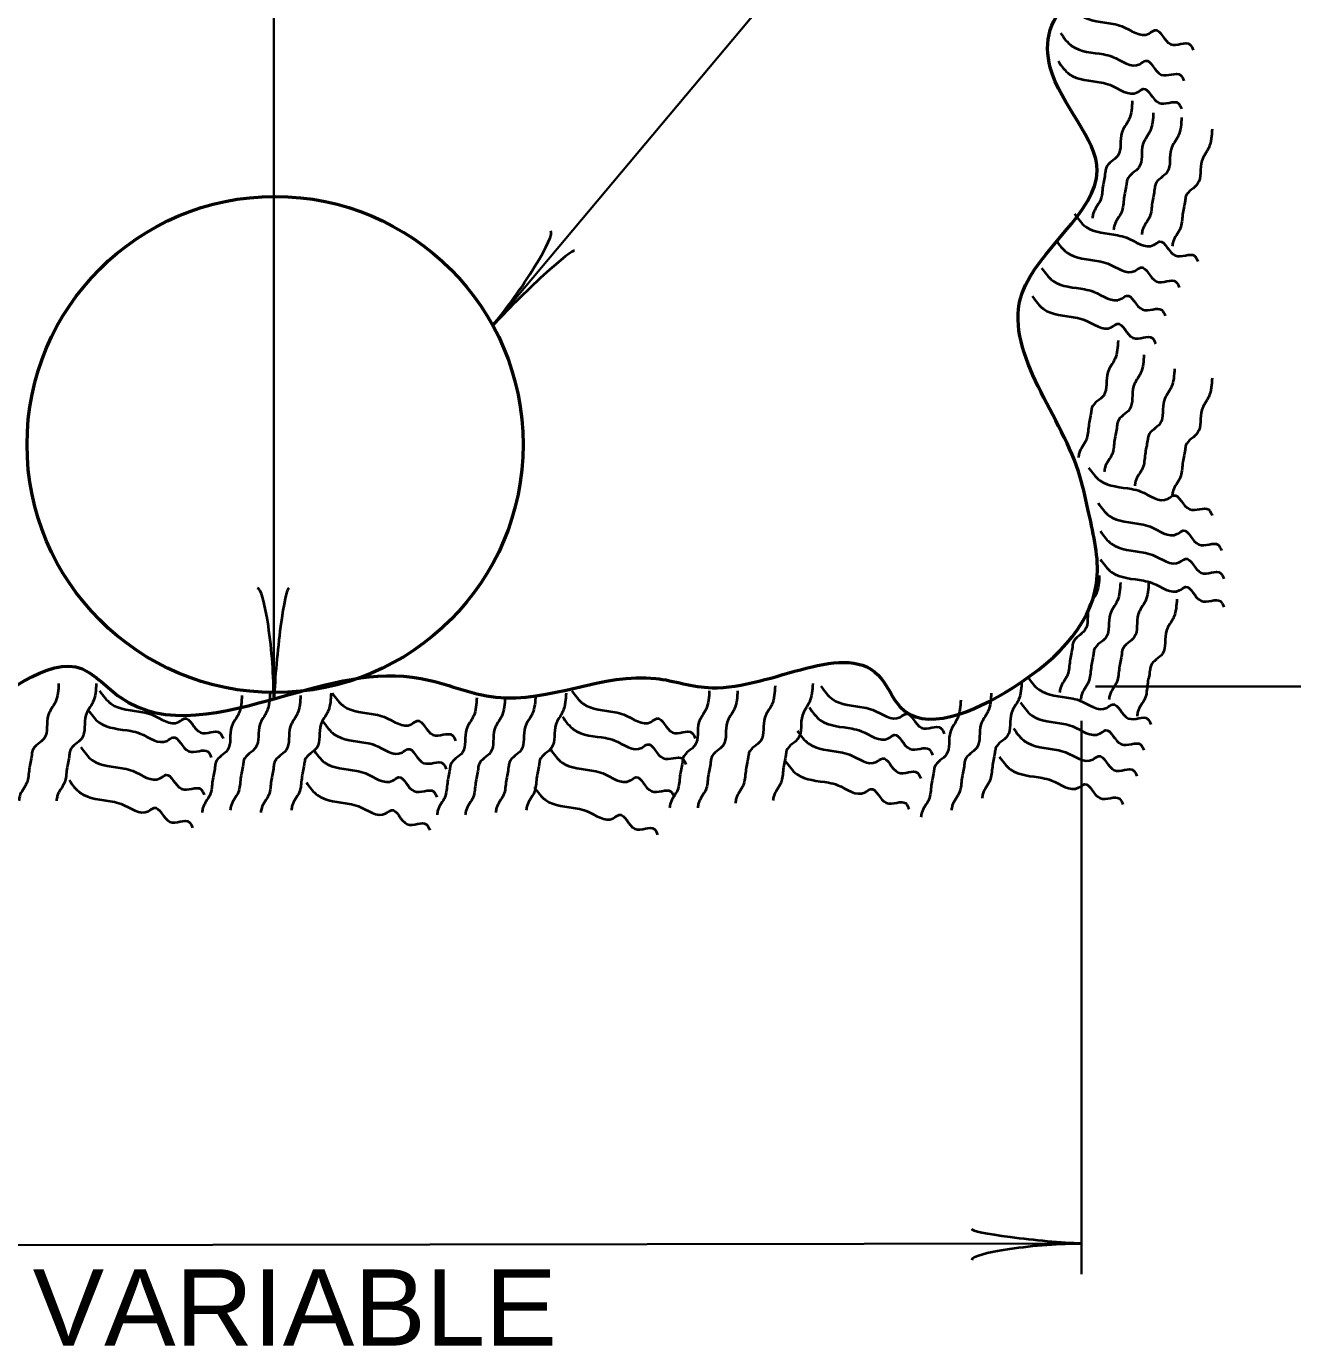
# Model space of a CAD drawing. Extents: x -488 to 193, y 19 to 459.
# Drawn here: x -199.23 to -166.05, y 207.54 to 242.11 of the extents above; entities that cross this region are included whole.
import ezdxf
from ezdxf.enums import TextEntityAlignment as Align

# ---------------------------------------------------------------- set-up
doc = ezdxf.new("R2010")
doc.units = 0
doc.header["$LTSCALE"] = 0.8
doc.layers.add('1', color=7, linetype='Continuous', lineweight=40)

msp = doc.modelspace()

# ---------------------------------------------------------------- linework, layer by layer
at = {"layer": '1', "lineweight": 35}
for p, q in [((-192.7425, 224.5147), (-192.7425, 263.8855)), ((-171.2137, 224.8116), (-138.2137, 224.8116)), ((-171.583, 223.9191), (-171.583, 209.4191)), ((-212.7047, 210.1614), (-171.583, 210.2216))]:
    msp.add_line(p, q, dxfattribs=at)
msp.add_lwpolyline([(-187.0093, 234.2723), (-174.6099, 249.0493), (-178.1099, 249.0493)], dxfattribs=at)
at = {"layer": '1', "lineweight": 53}
msp.add_circle((-192.7133, 231.1555), 6.5, dxfattribs=at)
at = {"layer": '1'}
for centre, major_axis, ratio, start_param, end_param in [((-186.5196, 235.2858), (-1.0282, -1.4683), 0.122415, 0.8963533, 3.1415927), ((-186.127, 234.9947), (1.2636, 1.2326), 0.07063, 6.2823074, 8.5597026), ((-193.0188, 225.6059), (0.1562, -1.7857), 0.122415, 0.8963533, 3.1415927), ((-193.0188, 225.6059), (0.1562, -1.7857), 0.122415, 0.8963533, 3.1415927), ((-192.5309, 225.6352), (0.1757, 1.7565), 0.07063, 6.2823074, 8.5597026), ((-192.5309, 225.6352), (0.1757, 1.7565), 0.07063, 6.2823074, 8.5597026), ((-172.7038, 210.4315), (1.7567, -0.1731), 0.07063, 3.1407148, 5.41811), ((-172.6738, 209.9437), (1.7855, 0.1588), 0.122415, 0.8963533, 3.1415927)]:
    msp.add_ellipse(centre, major_axis=major_axis, ratio=ratio, start_param=start_param, end_param=end_param, dxfattribs=at)
at = {"layer": '1', "lineweight": 53}
msp.add_spline([(-212.7425, 318.8428), (-213.2734, 312.6869), (-212.2884, 310.2246), (-213.2734, 308.0085), (-212.5347, 306.0386), (-213.2734, 303.3301), (-212.2884, 301.6064), (-212.0422, 299.3903), (-212.2884, 295.943), (-212.5347, 294.2194), (-213.5196, 292.9882), (-213.7658, 292.2495), (-213.2734, 291.0183), (-213.0272, 289.5409), (-212.7809, 287.8173), (-212.5347, 286.0937), (-212.5347, 284.1237), (-211.5497, 281.4152), (-211.796, 279.6916), (-212.2884, 278.7066), (-212.2884, 275.9981), (-212.0422, 272.797), (-212.2884, 271.5658), (-212.2884, 268.8572), (-212.7809, 265.41), (-212.7809, 262.9477), (-213.7658, 259.7466), (-213.0272, 258.0229), (-213.2734, 255.8068), (-213.5196, 253.0982), (-213.2734, 251.3746), (-213.0272, 248.4198), (-212.7809, 246.6962), (-213.0272, 244.7263), (-213.0272, 241.5252), (-212.2884, 240.7866), (-212.7809, 236.8468), (-212.7809, 234.6307), (-212.5347, 233.1532), (-213.0272, 230.1985), (-212.5347, 228.9673), (-213.0272, 226.7512), (-212.5347, 225.7662), (-210.5648, 223.7964), (-208.8412, 224.2888), (-207.1175, 225.52), (-205.6401, 224.2888), (-204.1627, 224.0426), (-200.9617, 224.0426), (-197.7606, 225.2738), (-196.7757, 224.5351), (-192.5897, 224.5351), (-188.8962, 225.0276), (-186.9263, 224.5351), (-182.7403, 225.0276), (-181.2629, 224.7813), (-176.8307, 225.0276), (-176.3382, 224.2888), (-173.3834, 224.7813), (-171.1673, 227.7362), (-171.4136, 229.4597), (-171.6598, 230.4447), (-173.1372, 235.1232), (-171.1673, 238.3242), (-172.3985, 241.0327), (-172.3985, 242.0177), (-171.4136, 243.7413), (-171.906, 246.4499), (-171.1673, 247.6811), (-170.1824, 250.1434), (-171.6598, 254.3294), (-171.6598, 255.8068), (-171.4136, 257.5305), (-172.1522, 259.7466), (-171.906, 261.224), (-172.1522, 263.9326), (-173.1372, 267.3798), (-171.6598, 270.0884), (-171.4136, 272.3045), (-171.1673, 275.9981), (-171.4136, 277.9679), (-172.1522, 279.6916), (-172.1522, 281.169), (-171.906, 284.1237), (-172.891, 287.0786), (-173.1372, 289.7872), (-171.4136, 292.4957), (-172.1522, 294.4656), (-172.3985, 295.6968), (-171.1673, 298.6516), (-172.1522, 300.8677), (-172.1522, 305.0537), (-171.906, 306.5311), (-171.6598, 308.0085), (-172.6447, 310.7171), (-172.891, 312.1945), (-172.7425, 318.8428)], degree=3, dxfattribs=at)
at = {"layer": '1'}
for points in [[(-171.8871, 242.7365), (-171.5942, 242.4029), (-170.7617, 242.1799), (-170.5238, 242.1162), (-169.8103, 241.925), (-169.6595, 242.0121), (-169.2474, 241.6468), (-168.74, 241.6382), (-168.6529, 241.4875)], [(-172.1333, 241.9363), (-171.8404, 241.6027), (-171.0079, 241.3797), (-170.7701, 241.316), (-170.0566, 241.1248), (-169.9057, 241.2118), (-169.4937, 240.8466), (-168.9862, 240.8379), (-168.8992, 240.6873)], [(-172.1949, 241.1975), (-171.902, 240.8639), (-171.0695, 240.6409), (-170.8317, 240.5772), (-170.1182, 240.386), (-169.9673, 240.4731), (-169.5553, 240.1078), (-169.0478, 240.0992), (-168.9607, 239.9485)], [(-170.2537, 240.157), (-170.3392, 239.6721), (-170.5246, 239.3297), (-170.6315, 238.7234), (-170.9382, 238.4025), (-170.9595, 238.2813), (-171.0237, 237.9175), (-171.0877, 237.5537), (-171.2732, 237.2115), (-171.2947, 237.0902)], [(-169.6997, 239.8492), (-169.7852, 239.3642), (-169.9705, 239.0219), (-170.0774, 238.4156), (-170.3842, 238.0947), (-170.4054, 237.9735), (-170.4696, 237.6097), (-170.5337, 237.2459), (-170.7192, 236.9037), (-170.7406, 236.7823)], [(-168.961, 239.7261), (-169.0465, 239.2412), (-169.2318, 238.8988), (-169.3388, 238.2925), (-169.6455, 237.9716), (-169.6668, 237.8504), (-169.7309, 237.4866), (-169.795, 237.1228), (-169.9805, 236.7806), (-170.0019, 236.6592)], [(-168.1608, 239.4183), (-168.2463, 238.9333), (-168.4316, 238.591), (-168.5385, 237.9847), (-168.8452, 237.6637), (-168.8665, 237.5426), (-168.9307, 237.1787), (-168.9947, 236.815), (-169.1803, 236.4727), (-169.2017, 236.3514)], [(-171.764, 237.1962), (-171.4711, 236.8626), (-170.6386, 236.6396), (-170.4007, 236.5759), (-169.6873, 236.3847), (-169.5364, 236.4717), (-169.1243, 236.1065), (-168.6169, 236.0978), (-168.5298, 235.9472)], [(-172.2564, 236.5191), (-171.9635, 236.1855), (-171.131, 235.9625), (-170.8932, 235.8988), (-170.1797, 235.7076), (-170.0288, 235.7947), (-169.6167, 235.4294), (-169.1093, 235.4207), (-169.0222, 235.2701)], [(-172.6258, 235.7803), (-172.3329, 235.4467), (-171.5004, 235.2237), (-171.2626, 235.1601), (-170.5491, 234.9688), (-170.3982, 235.0559), (-169.9862, 234.6907), (-169.4787, 234.682), (-169.3917, 234.5313)], [(-172.872, 235.0417), (-172.5791, 234.7081), (-171.7466, 234.4851), (-171.5087, 234.4214), (-170.7952, 234.2302), (-170.6444, 234.3173), (-170.2323, 233.952), (-169.7249, 233.9433), (-169.6378, 233.7927)], [(-170.6231, 233.878), (-170.7086, 233.3931), (-170.8939, 233.0507), (-171.0008, 232.4444), (-171.3076, 232.1235), (-171.3288, 232.0023), (-171.393, 231.6385), (-171.4571, 231.2747), (-171.6426, 230.9325), (-171.664, 230.8112)], [(-169.9459, 233.5087), (-170.0314, 233.0237), (-170.2167, 232.6814), (-170.3237, 232.0751), (-170.6304, 231.7542), (-170.6517, 231.633), (-170.7158, 231.2692), (-170.7799, 230.9054), (-170.9654, 230.5632), (-170.9868, 230.4418)], [(-169.1457, 233.1393), (-169.2312, 232.6544), (-169.4165, 232.3121), (-169.5234, 231.7057), (-169.8302, 231.3848), (-169.8514, 231.2637), (-169.9156, 230.8998), (-169.9797, 230.5361), (-170.1652, 230.1938), (-170.1866, 230.0725)], [(-168.1608, 232.8931), (-168.2463, 232.4082), (-168.4316, 232.0658), (-168.5385, 231.4595), (-168.8452, 231.1386), (-168.8665, 231.0174), (-168.9307, 230.6536), (-168.9947, 230.2898), (-169.1803, 229.9476), (-169.2017, 229.8262)], [(-171.3946, 230.5478), (-171.1017, 230.2142), (-170.2692, 229.9912), (-170.0313, 229.9276), (-169.3178, 229.7363), (-169.167, 229.8234), (-168.7549, 229.4582), (-168.2475, 229.4495), (-168.1604, 229.2988)], [(-171.1484, 229.6244), (-170.8555, 229.2908), (-170.023, 229.0678), (-169.7852, 229.0042), (-169.0717, 228.8129), (-168.9208, 228.9), (-168.5087, 228.5348), (-168.0013, 228.5261), (-167.9142, 228.3754)], [(-171.0868, 228.8858), (-170.7939, 228.5522), (-169.9614, 228.3292), (-169.7236, 228.2655), (-169.0101, 228.0743), (-168.8593, 228.1613), (-168.4472, 227.7961), (-167.9398, 227.7874), (-167.8527, 227.6368)], [(-171.0868, 228.147), (-170.7939, 227.8134), (-169.9614, 227.5904), (-169.7236, 227.5267), (-169.0101, 227.3355), (-168.8593, 227.4226), (-168.4472, 227.0573), (-167.9398, 227.0487), (-167.8527, 226.898)], [(-171.1156, 227.7222), (-171.2011, 227.2372), (-171.3864, 226.8949), (-171.4933, 226.2886), (-171.8001, 225.9677), (-171.8213, 225.8465), (-171.8855, 225.4827), (-171.9496, 225.1189), (-172.1351, 224.7767), (-172.1565, 224.6553)], [(-170.5616, 227.5374), (-170.6471, 227.0525), (-170.8324, 226.7102), (-170.9393, 226.1038), (-171.2461, 225.7829), (-171.2673, 225.6617), (-171.3315, 225.2979), (-171.3956, 224.9342), (-171.5811, 224.5919), (-171.6025, 224.4706)], [(-169.8228, 227.5374), (-169.9083, 227.0525), (-170.0937, 226.7102), (-170.2006, 226.1038), (-170.5073, 225.7829), (-170.5286, 225.6617), (-170.5927, 225.2979), (-170.6568, 224.9342), (-170.8423, 224.5919), (-170.8637, 224.4706)], [(-169.0842, 227.1066), (-169.1697, 226.6217), (-169.355, 226.2793), (-169.4619, 225.673), (-169.7687, 225.3521), (-169.7899, 225.2309), (-169.8541, 224.8671), (-169.9182, 224.5033), (-170.1037, 224.1611), (-170.1251, 224.0397)], [(-172.9952, 225.0692), (-172.7022, 224.7356), (-171.8697, 224.5126), (-171.6319, 224.4489), (-170.9184, 224.2577), (-170.7676, 224.3448), (-170.3555, 223.9795), (-169.8481, 223.9708), (-169.761, 223.8202)], [(-198.386, 224.8903), (-198.4715, 224.4054), (-198.6568, 224.0631), (-198.7637, 223.4567), (-199.0705, 223.1358), (-199.0917, 223.0147), (-199.1559, 222.6508), (-199.22, 222.2871), (-199.4055, 221.9448), (-199.4269, 221.8235)], [(-197.4011, 224.8903), (-197.4866, 224.4054), (-197.6719, 224.0631), (-197.7788, 223.4567), (-198.0856, 223.1358), (-198.1068, 223.0147), (-198.171, 222.6508), (-198.2351, 222.2871), (-198.4206, 221.9448), (-198.442, 221.8235)], [(-197.3107, 224.6997), (-197.0178, 224.3662), (-196.1853, 224.1432), (-195.9475, 224.0795), (-195.234, 223.8882), (-195.0832, 223.9753), (-194.6711, 223.6101), (-194.1637, 223.6014), (-194.0766, 223.4507)], [(-184.9376, 224.6997), (-184.6447, 224.3662), (-183.8122, 224.1432), (-183.5743, 224.0795), (-182.8608, 223.8882), (-182.71, 223.9753), (-182.2979, 223.6101), (-181.7905, 223.6014), (-181.7034, 223.4507)], [(-181.3342, 224.7057), (-181.4197, 224.2208), (-181.6051, 223.8785), (-181.712, 223.2722), (-182.0187, 222.9512), (-182.04, 222.8301), (-182.1042, 222.4663), (-182.1683, 222.1025), (-182.3537, 221.7602), (-182.3752, 221.6389)], [(-180.5956, 224.7057), (-180.6811, 224.2208), (-180.8664, 223.8785), (-180.9733, 223.2722), (-181.2801, 222.9512), (-181.3013, 222.8301), (-181.3655, 222.4663), (-181.4296, 222.1025), (-181.6151, 221.7602), (-181.6365, 221.6389)], [(-179.6107, 224.8288), (-179.6962, 224.3439), (-179.8815, 224.0016), (-179.9884, 223.3953), (-180.2952, 223.0743), (-180.3164, 222.9532), (-180.3806, 222.5893), (-180.4447, 222.2256), (-180.6302, 221.8833), (-180.6516, 221.762)], [(-178.6257, 224.8904), (-178.7113, 224.4055), (-178.8966, 224.0632), (-179.0035, 223.4568), (-179.3102, 223.1359), (-179.3315, 223.0147), (-179.3957, 222.6509), (-179.4597, 222.2872), (-179.6453, 221.9449), (-179.6667, 221.8236)], [(-178.4123, 224.8229), (-178.1194, 224.4893), (-177.2869, 224.2663), (-177.0491, 224.2027), (-176.3356, 224.0114), (-176.1848, 224.0985), (-175.7727, 223.7332), (-175.2652, 223.7246), (-175.1782, 223.5739)], [(-173.147, 224.952), (-173.2325, 224.4671), (-173.4178, 224.1248), (-173.5247, 223.5184), (-173.8315, 223.1975), (-173.8527, 223.0763), (-173.9169, 222.7125), (-173.981, 222.3487), (-174.1665, 222.0065), (-174.1879, 221.8852)], [(-193.5845, 224.5826), (-193.67, 224.0977), (-193.8553, 223.7553), (-193.9622, 223.149), (-194.269, 222.8281), (-194.2902, 222.7069), (-194.3544, 222.3431), (-194.4185, 221.9793), (-194.604, 221.6371), (-194.6254, 221.5157)], [(-192.8457, 224.6442), (-192.9313, 224.1592), (-193.1166, 223.8169), (-193.2235, 223.2106), (-193.5302, 222.8897), (-193.5515, 222.7685), (-193.6157, 222.4047), (-193.6797, 222.0409), (-193.8653, 221.6987), (-193.8867, 221.5773)], [(-192.0455, 224.5826), (-192.131, 224.0977), (-192.3163, 223.7553), (-192.4232, 223.149), (-192.73, 222.8281), (-192.7512, 222.7069), (-192.8154, 222.3431), (-192.8795, 221.9793), (-193.065, 221.6371), (-193.0864, 221.5157)], [(-191.2452, 224.6442), (-191.3307, 224.1592), (-191.5161, 223.8169), (-191.623, 223.2106), (-191.9297, 222.8897), (-191.951, 222.7685), (-192.0152, 222.4047), (-192.0793, 222.0409), (-192.2647, 221.6987), (-192.2862, 221.5773)], [(-191.2165, 224.6382), (-190.9236, 224.3046), (-190.0911, 224.0816), (-189.8533, 224.0179), (-189.1397, 223.8267), (-188.9889, 223.9137), (-188.5768, 223.5485), (-188.0694, 223.5398), (-187.9823, 223.3892)], [(-187.4286, 224.521), (-187.5141, 224.0361), (-187.6994, 223.6937), (-187.8063, 223.0874), (-188.1131, 222.7665), (-188.1343, 222.6453), (-188.1985, 222.2815), (-188.2626, 221.9177), (-188.4481, 221.5755), (-188.4695, 221.4542)], [(-186.6899, 224.521), (-186.7754, 224.0361), (-186.9607, 223.6937), (-187.0677, 223.0874), (-187.3744, 222.7665), (-187.3957, 222.6453), (-187.4598, 222.2815), (-187.5239, 221.9177), (-187.7094, 221.5755), (-187.7308, 221.4542)], [(-185.8896, 224.5826), (-185.9751, 224.0977), (-186.1604, 223.7553), (-186.2673, 223.149), (-186.5741, 222.8281), (-186.5953, 222.7069), (-186.6595, 222.3431), (-186.7236, 221.9793), (-186.9091, 221.6371), (-186.9305, 221.5157)], [(-185.0893, 224.6442), (-185.1748, 224.1592), (-185.3602, 223.8169), (-185.4671, 223.2106), (-185.7738, 222.8897), (-185.7951, 222.7685), (-185.8593, 222.4047), (-185.9233, 222.0409), (-186.1088, 221.6987), (-186.1302, 221.5773)], [(-174.7476, 224.4595), (-174.8331, 223.9746), (-175.0184, 223.6322), (-175.1253, 223.0259), (-175.4321, 222.705), (-175.4533, 222.5838), (-175.5175, 222.22), (-175.5816, 221.8562), (-175.7671, 221.514), (-175.7885, 221.3927)], [(-173.9473, 224.6442), (-174.0328, 224.1592), (-174.2182, 223.8169), (-174.3251, 223.2106), (-174.6318, 222.8897), (-174.6531, 222.7685), (-174.7173, 222.4047), (-174.7813, 222.0409), (-174.9668, 221.6987), (-174.9882, 221.5773)], [(-173.1798, 224.392), (-172.8869, 224.0584), (-172.0544, 223.8354), (-171.8166, 223.7717), (-171.1031, 223.5805), (-170.9522, 223.6676), (-170.5402, 223.3023), (-170.0327, 223.2937), (-169.9457, 223.143)], [(-197.6186, 224.2072), (-197.3257, 223.8737), (-196.4932, 223.6507), (-196.2553, 223.587), (-195.5418, 223.3957), (-195.391, 223.4828), (-194.9789, 223.1176), (-194.4715, 223.1089), (-194.3844, 222.9582)], [(-185.1838, 224.0226), (-184.8908, 223.689), (-184.0583, 223.466), (-183.8205, 223.4023), (-183.107, 223.2111), (-182.9562, 223.2982), (-182.5441, 222.9329), (-182.0367, 222.9243), (-181.9496, 222.7736)], [(-178.7202, 224.2688), (-178.4272, 223.9352), (-177.5948, 223.7122), (-177.3569, 223.6486), (-176.6434, 223.4573), (-176.4926, 223.5444), (-176.0805, 223.1792), (-175.5731, 223.1705), (-175.486, 223.0198)], [(-191.4627, 223.8995), (-191.1698, 223.5659), (-190.3373, 223.3429), (-190.0995, 223.2792), (-189.386, 223.088), (-189.2352, 223.1751), (-188.8231, 222.8098), (-188.3157, 222.8012), (-188.2286, 222.6505)], [(-179.0279, 223.6532), (-178.735, 223.3197), (-177.9025, 223.0967), (-177.6647, 223.033), (-176.9512, 222.8417), (-176.8003, 222.9288), (-176.3882, 222.5636), (-175.8808, 222.5549), (-175.7937, 222.4042)], [(-173.3645, 223.7148), (-173.0716, 223.3812), (-172.2391, 223.1582), (-172.0012, 223.0946), (-171.2877, 222.9033), (-171.1369, 222.9904), (-170.7248, 222.6252), (-170.2174, 222.6165), (-170.1303, 222.4658)], [(-197.8032, 223.2223), (-197.5103, 222.8887), (-196.6778, 222.6658), (-196.44, 222.6021), (-195.7265, 222.4108), (-195.5757, 222.4979), (-195.1636, 222.1327), (-194.6562, 222.124), (-194.5691, 221.9733)], [(-191.709, 223.1607), (-191.4161, 222.8272), (-190.5836, 222.6042), (-190.3457, 222.5405), (-189.6322, 222.3492), (-189.4814, 222.4363), (-189.0693, 222.0711), (-188.5619, 222.0624), (-188.4748, 221.9117)], [(-185.4916, 223.1607), (-185.1987, 222.8272), (-184.3662, 222.6042), (-184.1283, 222.5405), (-183.4148, 222.3492), (-183.264, 222.4363), (-182.8519, 222.0711), (-182.3445, 222.0624), (-182.2574, 221.9117)], [(-173.7338, 222.9762), (-173.4409, 222.6426), (-172.6084, 222.4196), (-172.3706, 222.3559), (-171.6571, 222.1647), (-171.5062, 222.2517), (-171.0942, 221.8865), (-170.5867, 221.8778), (-170.4997, 221.7272)], [(-179.3357, 222.853), (-179.0428, 222.5194), (-178.2103, 222.2964), (-177.9725, 222.2327), (-177.259, 222.0415), (-177.1082, 222.1286), (-176.6961, 221.7633), (-176.1887, 221.7547), (-176.1016, 221.604)], [(-198.111, 222.3605), (-197.8181, 222.0269), (-196.9856, 221.8039), (-196.7477, 221.7403), (-196.0342, 221.549), (-195.8834, 221.6361), (-195.4713, 221.2708), (-194.9639, 221.2622), (-194.8768, 221.1115)], [(-191.8937, 222.2989), (-191.6008, 221.9653), (-190.7682, 221.7423), (-190.5304, 221.6787), (-189.8169, 221.4874), (-189.6661, 221.5745), (-189.254, 221.2092), (-188.7466, 221.2006), (-188.6595, 221.0499)], [(-185.9225, 222.1758), (-185.6296, 221.8422), (-184.7971, 221.6192), (-184.5592, 221.5556), (-183.8457, 221.3643), (-183.6949, 221.4514), (-183.2828, 221.0862), (-182.7754, 221.0775), (-182.6883, 220.9268)]]:
    msp.add_spline(points, degree=3, dxfattribs=at)

# ---------------------------------------------------------------- texts
at = {"layer": '1', "width": 1.05}
msp.add_text('VARIABLE', height=2, dxfattribs=at).set_placement((-192.1979, 207.5443), align=Align.CENTER)

doc.saveas('drawing.dxf')
